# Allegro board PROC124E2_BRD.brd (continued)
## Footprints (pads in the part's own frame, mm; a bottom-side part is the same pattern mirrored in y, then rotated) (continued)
SON6_SN74LVC2G17_40X60_0-6
  rect 0.356x0.203 smd: 1(-0.275,0.5)
  rect 0.305x0.203 smd: 2(-0.3,0) 3(-0.3,-0.5) 4(0.3,-0.5) 5(0.3,0) 6(0.3,0.5)
SON8_25-59_130X130_1
  rect 0.762x0.356 smd: 1(-1.45,0.975) 2(-1.45,0.325) 3(-1.45,-0.325) 4(-1.45,-0.975) 5(1.45,-0.975) 6(1.45,-0.325) 7(1.45,0.325) 8(1.45,0.975)
  rect 1.753x2.515 smd: 9(0,0)
SOT23-5
  rect 0.889x0.559 smd: 1(-1.2,0.95) 2(-1.2,0) 3(-1.2,-0.95) 4(1.2,-0.95) 5(1.2,0.95)
SOT23-6
  rect 1.041x0.61 smd: 1(-1.35,0.95) 2(-1.35,0) 3(-1.35,-0.95) 4(1.35,-0.95) 5(1.35,0) 6(1.35,0.95)
SOT23-6_1-5
  rect 1.092x0.61 smd: 1(-1.35,0.95) 2(-1.35,0) 3(-1.35,-0.95) 4(1.35,-0.95) 5(1.35,0) 6(1.35,0.95)
SOT23-123_1-2
  rect 1.016x0.61 smd: 1(-1.15,0.95) 2(-1.15,-0.95) 3(1.15,0)
SOT553-5_0-6
  rect 0.559x0.229 smd: 1(-0.69,0.5) 2(-0.69,0) 3(-0.69,-0.5) 4(0.69,-0.5) 5(0.69,0.5)
SW4_100X216_200X200_SMD_4-2
  rect 1.27x1.27 smd: 1(-1.27,-2.75) 2(1.27,-2.75) 3(1.27,2.75) 4(-1.27,2.75)
SW16_416131160808_460X230_SMD_2-7
  rect 0.762x1.27 smd: 1(-4.445,-3.81) 2(-3.175,-3.81) 3(-1.905,-3.81) 4(-0.635,-3.81) 5(0.635,-3.81) 6(1.905,-3.81) 7(3.175,-3.81) 8(4.445,-3.81) 9(4.445,3.81) 10(3.175,3.81) 11(1.905,3.81) 12(0.635,3.81) 13(-0.635,3.81) 14(-1.905,3.81) 15(-3.175,3.81) 16(-4.445,3.81)
TFBGA200_MT53E1G16D1FW_400X570_1-1
  round 0.33 smd: A1(-4.4,6.825) A2(-3.6,6.825) A3(-2.8,6.825) A4(-2,6.825) A5(-1.2,6.825) A8(1.2,6.825) A9(2,6.825) A10(2.8,6.825) A11(3.6,6.825) A12(4.4,6.825) AA1(-4.4,-6.175) AA2(-3.6,-6.175) AA3(-2.8,-6.175) AA4(-2,-6.175) AA5(-1.2,-6.175) AA8(1.2,-6.175) AA9(2,-6.175) AA10(2.8,-6.175) AA11(3.6,-6.175) AA12(4.4,-6.175) AB1(-4.4,-6.825) AB2(-3.6,-6.825) AB3(-2.8,-6.825) AB4(-2,-6.825) AB5(-1.2,-6.825) AB8(1.2,-6.825) AB9(2,-6.825) AB10(2.8,-6.825) AB11(3.6,-6.825) AB12(4.4,-6.825) B1(-4.4,6.175) B2(-3.6,6.175) B3(-2.8,6.175) B4(-2,6.175) B5(-1.2,6.175) B8(1.2,6.175) B9(2,6.175) B10(2.8,6.175) B11(3.6,6.175) B12(4.4,6.175) C1(-4.4,5.525) C2(-3.6,5.525) C3(-2.8,5.525) C4(-2,5.525) C5(-1.2,5.525) C8(1.2,5.525) C9(2,5.525) C10(2.8,5.525) C11(3.6,5.525) C12(4.4,5.525) D1(-4.4,4.875) D2(-3.6,4.875) D3(-2.8,4.875) D4(-2,4.875) D5(-1.2,4.875) D8(1.2,4.875) D9(2,4.875) D10(2.8,4.875) D11(3.6,4.875) D12(4.4,4.875) E1(-4.4,4.225) E2(-3.6,4.225) E3(-2.8,4.225) E4(-2,4.225) E5(-1.2,4.225) E8(1.2,4.225) E9(2,4.225) E10(2.8,4.225) E11(3.6,4.225) E12(4.4,4.225) F1(-4.4,3.575) F2(-3.6,3.575) F3(-2.8,3.575) F4(-2,3.575) F5(-1.2,3.575) F8(1.2,3.575) F9(2,3.575) F10(2.8,3.575) F11(3.6,3.575) F12(4.4,3.575) G1(-4.4,2.925) G2(-3.6,2.925) G3(-2.8,2.925) G4(-2,2.925) G5(-1.2,2.925) G8(1.2,2.925) G9(2,2.925) G10(2.8,2.925) G11(3.6,2.925) G12(4.4,2.925) H1(-4.4,2.275) H2(-3.6,2.275) H3(-2.8,2.275) H4(-2,2.275) H5(-1.2,2.275) H8(1.2,2.275) H9(2,2.275) H10(2.8,2.275) H11(3.6,2.275) H12(4.4,2.275) J1(-4.4,1.625) J2(-3.6,1.625) J3(-2.8,1.625) J4(-2,1.625) J5(-1.2,1.625) J8(1.2,1.625) J9(2,1.625) J10(2.8,1.625) J11(3.6,1.625) J12(4.4,1.625) K1(-4.4,0.975) K2(-3.6,0.975) K3(-2.8,0.975) K4(-2,0.975) K5(-1.2,0.975) K8(1.2,0.975) K9(2,0.975) K10(2.8,0.975) K11(3.6,0.975) K12(4.4,0.975) N1(-4.4,-0.975) N2(-3.6,-0.975) N3(-2.8,-0.975) N4(-2,-0.975) N5(-1.2,-0.975) N8(1.2,-0.975) N9(2,-0.975) N10(2.8,-0.975) N11(3.6,-0.975) N12(4.4,-0.975) P1(-4.4,-1.625) P2(-3.6,-1.625) P3(-2.8,-1.625) P4(-2,-1.625) P5(-1.2,-1.625) P8(1.2,-1.625) P9(2,-1.625) P10(2.8,-1.625) P11(3.6,-1.625) P12(4.4,-1.625) R1(-4.4,-2.275) R2(-3.6,-2.275) R3(-2.8,-2.275) R4(-2,-2.275) R5(-1.2,-2.275) R8(1.2,-2.275) R9(2,-2.275) R10(2.8,-2.275) R11(3.6,-2.275) R12(4.4,-2.275) T1(-4.4,-2.925) T2(-3.6,-2.925) T3(-2.8,-2.925) T4(-2,-2.925) T5(-1.2,-2.925) T8(1.2,-2.925) T9(2,-2.925) T10(2.8,-2.925) T11(3.6,-2.925) T12(4.4,-2.925) U1(-4.4,-3.575) U2(-3.6,-3.575) U3(-2.8,-3.575) U4(-2,-3.575) U5(-1.2,-3.575) U8(1.2,-3.575) U9(2,-3.575) U10(2.8,-3.575) U11(3.6,-3.575) U12(4.4,-3.575) V1(-4.4,-4.225) V2(-3.6,-4.225) V3(-2.8,-4.225) V4(-2,-4.225) V5(-1.2,-4.225) V8(1.2,-4.225) V9(2,-4.225) V10(2.8,-4.225) V11(3.6,-4.225) V12(4.4,-4.225) W1(-4.4,-4.875) W2(-3.6,-4.875) W3(-2.8,-4.875) W4(-2,-4.875) W5(-1.2,-4.875) W8(1.2,-4.875) W9(2,-4.875) W10(2.8,-4.875) W11(3.6,-4.875) W12(4.4,-4.875) Y1(-4.4,-5.525) Y2(-3.6,-5.525) Y3(-2.8,-5.525) Y4(-2,-5.525) Y5(-1.2,-5.525) Y8(1.2,-5.525) Y9(2,-5.525) Y10(2.8,-5.525) Y11(3.6,-5.525) Y12(4.4,-5.525)
TO_SOT23-123
  rect 1.016x1.397 smd: 1(-0.95,-1.1) 2(0.95,-1.1) 3(0,1.1)
TP20_SMD
  round 0.457 smd: 1(0,0)
TP_40X65
  round 1.651 hole 1.016: 1(0,0)
TPBGA24_39-37_240X320_1-2
  round 0.356 smd: A2(-1,2) A3(0,2) A4(1,2) A5(2,2) B1(-2,1) B2(-1,1) B3(0,1) B4(1,1) B5(2,1) C1(-2,0) C2(-1,0) C3(0,0) C4(1,0) C5(2,0) D1(-2,-1) D2(-1,-1) D3(0,-1) D4(1,-1) D5(2,-1) E1(-2,-2) E2(-1,-2) E3(0,-2) E4(1,-2) E5(2,-2)
TQFP128_15-74_550X550_1-2
  rect 1.499x0.203 smd: 1(-7.7,6.2) 2(-7.7,5.8) 3(-7.7,5.4) 4(-7.7,5) 5(-7.7,4.6) 6(-7.7,4.2) 7(-7.7,3.8) 8(-7.7,3.4) 9(-7.7,3) 10(-7.7,2.6) 11(-7.7,2.2) 12(-7.7,1.8) 13(-7.7,1.4) 14(-7.7,1) 15(-7.7,0.6) 16(-7.7,0.2) 17(-7.7,-0.2) 18(-7.7,-0.6) 19(-7.7,-1) 20(-7.7,-1.4) 21(-7.7,-1.8) 22(-7.7,-2.2) 23(-7.7,-2.6) 24(-7.7,-3) 25(-7.7,-3.4) 26(-7.7,-3.8) 27(-7.7,-4.2) 28(-7.7,-4.6) 29(-7.7,-5) 30(-7.7,-5.4) 31(-7.7,-5.8) 32(-7.7,-6.2) 65(7.7,-6.2) 66(7.7,-5.8) 67(7.7,-5.4) 68(7.7,-5) 69(7.7,-4.6) 70(7.7,-4.2) 71(7.7,-3.8) 72(7.7,-3.4) 73(7.7,-3) 74(7.7,-2.6) 75(7.7,-2.2) 76(7.7,-1.8) 77(7.7,-1.4) 78(7.7,-1) 79(7.7,-0.6) 80(7.7,-0.2) 81(7.7,0.2) 82(7.7,0.6) 83(7.7,1) 84(7.7,1.4) 85(7.7,1.8) 86(7.7,2.2) 87(7.7,2.6) 88(7.7,3) 89(7.7,3.4) 90(7.7,3.8) 91(7.7,4.2) 92(7.7,4.6) 93(7.7,5) 94(7.7,5.4) 95(7.7,5.8) 96(7.7,6.2)
  rect 0.203x1.499 smd: 33(-6.2,-7.7) 34(-5.8,-7.7) 35(-5.4,-7.7) 36(-5,-7.7) 37(-4.6,-7.7) 38(-4.2,-7.7) 39(-3.8,-7.7) 40(-3.4,-7.7) 41(-3,-7.7) 42(-2.6,-7.7) 43(-2.2,-7.7) 44(-1.8,-7.7) 45(-1.4,-7.7) 46(-1,-7.7) 47(-0.6,-7.7) 48(-0.2,-7.7) 49(0.2,-7.7) 50(0.6,-7.7) 51(1,-7.7) 52(1.4,-7.7) 53(1.8,-7.7) 54(2.2,-7.7) 55(2.6,-7.7) 56(3,-7.7) 57(3.4,-7.7) 58(3.8,-7.7) 59(4.2,-7.7) 60(4.6,-7.7) 61(5,-7.7) 62(5.4,-7.7) 63(5.8,-7.7) 64(6.2,-7.7) 97(6.2,7.7) 98(5.8,7.7) 99(5.4,7.7) 100(5,7.7) 101(4.6,7.7) 102(4.2,7.7) 103(3.8,7.7) 104(3.4,7.7) 105(3,7.7) 106(2.6,7.7) 107(2.2,7.7) 108(1.8,7.7) 109(1.4,7.7) 110(1,7.7) 111(0.6,7.7) 112(0.2,7.7) 113(-0.2,7.7) 114(-0.6,7.7) 115(-1,7.7) 116(-1.4,7.7) 117(-1.8,7.7) 118(-2.2,7.7) 119(-2.6,7.7) 120(-3,7.7) 121(-3.4,7.7) 122(-3.8,7.7) 123(-4.2,7.7) 124(-4.6,7.7) 125(-5,7.7) 126(-5.4,7.7) 127(-5.8,7.7) 128(-6.2,7.7)
TSSOP8_25-59_125X180_1-2
  rect 1.499x0.457 smd: 1(-2.9,0.975) 2(-2.9,0.325) 3(-2.9,-0.325) 4(-2.9,-0.975) 5(2.9,-0.975) 6(2.9,-0.325) 7(2.9,0.325) 8(2.9,0.975)
TSSOP14_25-59_205X180_1-2
  rect 1.499x0.457 smd: 1(-2.9,1.95) 2(-2.9,1.3) 3(-2.9,0.65) 4(-2.9,0) 5(-2.9,-0.65) 6(-2.9,-1.3) 7(-2.9,-1.95) 8(2.9,-1.95) 9(2.9,-1.3) 10(2.9,-0.65) 11(2.9,0) 12(2.9,0.65) 13(2.9,1.3) 14(2.9,1.95)
TSSOP16_25-59_205X180
  rect 1.6x0.356 smd: 1(-2.8,2.275) 2(-2.8,1.625) 3(-2.8,0.975) 4(-2.8,0.325) 5(-2.8,-0.325) 6(-2.8,-0.975) 7(-2.8,-1.625) 8(-2.8,-2.275) 9(2.8,-2.275) 10(2.8,-1.625) 11(2.8,-0.975) 12(2.8,-0.325) 13(2.8,0.325) 14(2.8,0.975) 15(2.8,1.625) 16(2.8,2.275)
TSSOP24_25-59_315X180_1-2
  rect 1.448x0.457 smd: 1(-2.9,3.575) 2(-2.9,2.925) 3(-2.9,2.275) 4(-2.9,1.625) 5(-2.9,0.975) 6(-2.9,0.325) 7(-2.9,-0.325) 8(-2.9,-0.975) 9(-2.9,-1.625) 10(-2.9,-2.275) 11(-2.9,-2.925) 12(-2.9,-3.575) 13(2.9,-3.575) 14(2.9,-2.925) 15(2.9,-2.275) 16(2.9,-1.625) 17(2.9,-0.975) 18(2.9,-0.325) 19(2.9,0.325) 20(2.9,0.975) 21(2.9,1.625) 22(2.9,2.275) 23(2.9,2.925) 24(2.9,3.575)
UFDFPN8_M24512_120X80_0-6
  rect 0.61x0.305 smd: 1(-1.3,0.75) 2(-1.3,0.25) 3(-1.3,-0.25) 4(-1.3,-0.75) 5(1.3,-0.75) 6(1.3,-0.25) 7(1.3,0.25) 8(1.3,0.75)
  rect 1.194x1.397 smd: 9(0,0)
unnamed#2
  round 2.616 hole 2.743 unplated: (0,0)
unnamed#3
  round 1.549 hole 1.676 unplated: (-9.962,9.962) (-9.962,-9.962) (9.962,9.962) (9.962,-9.962)
  round 0.737 hole 0.864 unplated: (-4.882,-9.962) (9.962,7.422)
UQFN10_19-68_80X60_0-6
  rect 0.584x0.305 smd: 1(-0.635,0.75) 4(-0.635,-0.75) 6(0.635,-0.75) 9(0.635,0.75)
  rect 0.584x0.254 smd: 2(-0.635,0.25) 3(-0.635,-0.25) 7(0.635,-0.25) 8(0.635,0.25)
  rect 0.305x0.635 smd: 5(0,-0.86) 10(0,0.86)
UQFN12_TXB0104RUT_70X80_0-6
  custom 0.102x0.102 smd: 1(-0.65,0.8)
  rect 0.61x0.203 smd: 2(-0.65,0.4) 3(-0.65,0) 4(-0.65,-0.4) 5(-0.65,-0.8) 7(0.65,-0.8) 8(0.65,-0.4) 9(0.65,0) 10(0.65,0.4) 11(0.65,0.8)
  rect 0.203x0.61 smd: 6(0,-0.8) 12(0,0.8)
UQFN16_TMUX1574_70X100_0-6
  rect 0.711x0.203 smd: 1(-0.75,0.6)
  rect 0.61x0.203 smd: 2(-0.8,0.2) 3(-0.8,-0.2) 4(-0.8,-0.6) 9(0.8,-0.6) 10(0.8,-0.2) 11(0.8,0.2) 12(0.8,0.6)
  rect 0.203x0.61 smd: 5(-0.6,-1.2) 6(-0.2,-1.2) 7(0.2,-1.2) 8(0.6,-1.2) 13(0.6,1.2) 14(0.2,1.2) 15(-0.2,1.2) 16(-0.6,1.2)
VFBGA153_19-68_460X520_1-1
  round 0.254 smd: A1(-3.25,3.25) A2(-2.75,3.25) A3(-2.25,3.25) A4(-1.75,3.25) A5(-1.25,3.25) A6(-0.75,3.25) A7(-0.25,3.25) A8(0.25,3.25) A9(0.75,3.25) A10(1.25,3.25) A11(1.75,3.25) A12(2.25,3.25) A13(2.75,3.25) A14(3.25,3.25) B2(-2.75,2.75) B3(-2.25,2.75) B4(-1.75,2.75) B5(-1.25,2.75) B6(-0.75,2.75) B7(-0.25,2.75) B8(0.25,2.75) B9(0.75,2.75) B10(1.25,2.75) B11(1.75,2.75) B12(2.25,2.75) B13(2.75,2.75) B14(3.25,2.75) C2(-2.75,2.25) C3(-2.25,2.25) C4(-1.75,2.25) C5(-1.25,2.25) C6(-0.75,2.25) C7(-0.25,2.25) C8(0.25,2.25) C9(0.75,2.25) C10(1.25,2.25) C11(1.75,2.25) C12(2.25,2.25) C13(2.75,2.25) C14(3.25,2.25) D2(-2.75,1.75) D3(-2.25,1.75) D4(-1.75,1.75) D12(2.25,1.75) D13(2.75,1.75) D14(3.25,1.75) E1(-3.25,1.25) E2(-2.75,1.25) E3(-2.25,1.25) E5(-1.25,1.25) E6(-0.75,1.25) E7(-0.25,1.25) E8(0.25,1.25) E9(0.75,1.25) E10(1.25,1.25) E12(2.25,1.25) E13(2.75,1.25) E14(3.25,1.25) F1(-3.25,0.75) F2(-2.75,0.75) F3(-2.25,0.75) F5(-1.25,0.75) F10(1.25,0.75) F12(2.25,0.75) F13(2.75,0.75) F14(3.25,0.75) G1(-3.25,0.25) G2(-2.75,0.25) G3(-2.25,0.25) G5(-1.25,0.25) G10(1.25,0.25) G12(2.25,0.25) G13(2.75,0.25) G14(3.25,0.25) H1(-3.25,-0.25) H2(-2.75,-0.25) H3(-2.25,-0.25) H5(-1.25,-0.25) H10(1.25,-0.25) H12(2.25,-0.25) H13(2.75,-0.25) H14(3.25,-0.25) J1(-3.25,-0.75) J2(-2.75,-0.75) J3(-2.25,-0.75) J5(-1.25,-0.75) J10(1.25,-0.75) J12(2.25,-0.75) J13(2.75,-0.75) J14(3.25,-0.75) K1(-3.25,-1.25) K2(-2.75,-1.25) K3(-2.25,-1.25) K5(-1.25,-1.25) K6(-0.75,-1.25) K7(-0.25,-1.25) K8(0.25,-1.25) K9(0.75,-1.25) K10(1.25,-1.25) K12(2.25,-1.25) K13(2.75,-1.25) K14(3.25,-1.25) L1(-3.25,-1.75) L2(-2.75,-1.75) L3(-2.25,-1.75) L12(2.25,-1.75) L13(2.75,-1.75) L14(3.25,-1.75) M2(-2.75,-2.25) M3(-2.25,-2.25) M4(-1.75,-2.25) M5(-1.25,-2.25) M6(-0.75,-2.25) M7(-0.25,-2.25) M8(0.25,-2.25) M9(0.75,-2.25) M10(1.25,-2.25) M11(1.75,-2.25) M12(2.25,-2.25) M13(2.75,-2.25) M14(3.25,-2.25) N2(-2.75,-2.75) N3(-2.25,-2.75) N4(-1.75,-2.75) N5(-1.25,-2.75) N6(-0.75,-2.75) N7(-0.25,-2.75) N8(0.25,-2.75) N9(0.75,-2.75) N10(1.25,-2.75) N11(1.75,-2.75) N12(2.25,-2.75) N13(2.75,-2.75) N14(3.25,-2.75) P2(-2.75,-3.25) P3(-2.25,-3.25) P4(-1.75,-3.25) P5(-1.25,-3.25) P6(-0.75,-3.25) P7(-0.25,-3.25) P8(0.25,-3.25) P9(0.75,-3.25) P10(1.25,-3.25) P11(1.75,-3.25) P12(2.25,-3.25) P13(2.75,-3.25) P14(3.25,-3.25)
  round 0.203 smd: B1(-3.25,2.75) C1(-3.25,2.25) D1(-3.25,1.75) M1(-3.25,-2.25) N1(-3.25,-2.75) P1(-3.25,-3.25)
VQFN48_19-68_285X285
  rect 0.864x0.305 smd: 1(-3.5,2.75) 2(-3.5,2.25) 3(-3.5,1.75) 4(-3.5,1.25) 5(-3.5,0.75) 6(-3.5,0.25) 7(-3.5,-0.25) 8(-3.5,-0.75) 9(-3.5,-1.25) 10(-3.5,-1.75) 11(-3.5,-2.25) 12(-3.5,-2.75) 25(3.5,-2.75) 26(3.5,-2.25) 27(3.5,-1.75) 28(3.5,-1.25) 29(3.5,-0.75) 30(3.5,-0.25) 31(3.5,0.25) 32(3.5,0.75) 33(3.5,1.25) 34(3.5,1.75) 35(3.5,2.25) 36(3.5,2.75)
  rect 0.305x0.864 smd: 13(-2.75,-3.5) 14(-2.25,-3.5) 15(-1.75,-3.5) 16(-1.25,-3.5) 17(-0.75,-3.5) 18(-0.25,-3.5) 19(0.25,-3.5) 20(0.75,-3.5) 21(1.25,-3.5) 22(1.75,-3.5) 23(2.25,-3.5) 24(2.75,-3.5) 37(2.75,3.5) 38(2.25,3.5) 39(1.75,3.5) 40(1.25,3.5) 41(0.75,3.5) 42(0.25,3.5) 43(-0.25,3.5) 44(-0.75,3.5) 45(-1.25,3.5) 46(-1.75,3.5) 47(-2.25,3.5) 48(-2.75,3.5)
  rect 4.166x4.166 smd: 49(0,0)
VQFN56_TPS65987D_280X280_1
  rect 0.813x0.711 smd: 1(-3.35,2.4) 3(-3.35,1.6) 11(-3.35,-1.6) 13(-3.35,-2.4)
  rect 0.711x0.203 smd: 5(-3.35,1) 6(-3.35,0.6) 7(-3.35,0.2) 8(-3.35,-0.2) 9(-3.35,-0.6) 10(-3.35,-1) 29(3.35,-2.6) 30(3.35,-2.2) 31(3.35,-1.8) 32(3.35,-1.4) 33(3.35,-1) 34(3.35,-0.6) 35(3.35,-0.2) 36(3.35,0.2) 37(3.35,0.6) 38(3.35,1) 39(3.35,1.4) 40(3.35,1.8) 41(3.35,2.2) 42(3.35,2.6)
  rect 0.203x0.711 smd: 15(-2.6,-3.35) 16(-2.2,-3.35) 17(-1.8,-3.35) 18(-1.4,-3.35) 19(-1,-3.35) 20(-0.6,-3.35) 21(-0.2,-3.35) 22(0.2,-3.35) 23(0.6,-3.35) 24(1,-3.35) 25(1.4,-3.35) 26(1.8,-3.35) 27(2.2,-3.35) 28(2.6,-3.35) 43(2.6,3.35) 44(2.2,3.35) 45(1.8,3.35) 46(1.4,3.35) 47(1,3.35) 48(0.6,3.35) 49(0.2,3.35) 50(-0.2,3.35) 51(-0.6,3.35) 52(-1,3.35) 53(-1.4,3.35) 54(-1.8,3.35) 55(-2.2,3.35) 56(-2.6,3.35)
  rect 1.753x2.591 smd: 57(-1.875,1.45)
  rect 1.753x2.54 smd: 58(-1.875,-1.475)
  rect 3.404x5.512 smd: 59(1.05,0)
VQFNHR14_LM61460_160X140_1
  custom 0.175x0.175 smd: 1(-1.675,1.15) 5(-1.675,-1.15)
  rect 0.711x0.254 smd: 2(-1.85,0.525) 4(-1.85,-0.525)
  rect 0.711x0.305 smd: 3(-1.85,0)
  rect 0.254x0.711 smd: 6(-1.125,-1.6) 7(-0.625,-1.6) 13(-0.625,1.6) 14(-1.125,1.6)
  rect 0.406x0.991 smd: 8(0.45,-1.45) 12(0.45,1.45)
  custom 0.2x0.2 smd: 9(1.6,-1.15) 11(1.6,1.15)
  rect 2.388x0.406 smd: 10(1,0)
VQFNHR15_TPS630701_100X120_1
  rect 0.61x0.254 smd: 1(-1.15,0.75) 2(-1.15,0.25) 3(-1.15,-0.25) 4(-1.15,-0.75)
  rect 0.254x0.61 smd: 5(-0.725,-1.4) 6(-0.225,-1.4) 14(-0.225,1.4) 15(-0.725,1.4)
  rect 0.838x0.711 smd: 7(0.525,-1.4) 12(0.525,1.4)
  rect 1.448x0.356 smd: 9(0.775,-0.5) 11(0.775,0.5)
  rect 1.803x0.356 smd: 10(0.6,0)
VSONHR6_TPS62826_60X60_1
  rect 0.711x0.356 smd: 1(-0.65,0.5) 2(-0.65,0) 3(-0.65,-0.5)
  rect 0.991x0.203 smd: 4(0.45,-0.5) 5(0.45,0) 6(0.45,0.5)
VSSOP8_19-68_85X95
  rect 1.041x0.305 smd: 1(-1.65,0.75) 2(-1.65,0.25) 3(-1.65,-0.25) 4(-1.65,-0.75) 5(1.65,-0.75) 6(1.65,-0.25) 7(1.65,0.25) 8(1.65,0.75)
VSSOP8_19-68_85X95_0-9
  rect 0.838x0.305 smd: 1(-1.55,0.75) 2(-1.55,0.25) 3(-1.55,-0.25) 4(-1.55,-0.75) 5(1.55,-0.75) 6(1.55,-0.25) 7(1.55,0.25) 8(1.55,0.75)
WSON6_19-68_60X60
  rect 0.965x0.305 smd: 1(-0.65,0.5) 2(-0.65,0) 3(-0.65,-0.5) 4(0.65,-0.5) 5(0.65,0) 6(0.65,0.5)
WSON6_CSD13202Q2_80X80_0-8
  rect 0.457x0.305 smd: 1(-0.975,0.65) 2(-0.975,0) 3(-0.975,-0.65) 4(0.975,-0.65) 5(0.975,0) 6(0.975,0.65)
  rect 0.762x0.305 smd: 7(0.095,-0.65)
  rect 0.991x0.94 smd: 8(0,0.325)
WSON8_19-68_80X80_0-8
  rect 0.711x0.305 smd: 1(-1.05,0.75) 2(-1.05,0.25) 3(-1.05,-0.25) 4(-1.05,-0.75) 5(1.05,-0.75) 6(1.05,-0.25) 7(1.05,0.25) 8(1.05,0.75)
  rect 0.965x1.702 smd: 9(0,0)
WSON10_19-68_80X120_0-8
  rect 0.711x0.305 smd: 1(-1.05,1) 2(-1.05,0.5) 3(-1.05,0) 4(-1.05,-0.5) 5(-1.05,-1) 6(1.05,-1) 7(1.05,-0.5) 8(1.05,0) 9(1.05,0.5) 10(1.05,1)
  rect 0.94x2.489 smd: 11(0,0)
X2SON3_ESD122DMX_30X40_0-4
  rect 0.203x0.203 smd: 1(-0.15,0) 2(0.15,-0.34) 3(0.15,0.34)
X2SON4_TLV71318P_40X40_0-4
  custom 0.077x0.077 smd: 1(-0.43,0.325) 2(-0.43,-0.325) 3(0.43,-0.325) 4(0.43,0.325)
  rect 0.584x0.584 smd rot 45: 5(0,0)
X2SON5_TLV7021_30X30_0-4
  custom 0.08x0.08 smd: 1(-0.39,0.24) 2(-0.39,-0.24) 4(0.39,-0.24) 5(0.39,0.24)
  rect 0.356x0.356 smd rot 135: 3(0,0)
X2SON8_15-74_70X50
  rect 0.838x0.203 smd: 1(-0.55,0.6) 2(-0.55,0.2) 3(-0.55,-0.2) 4(-0.55,-0.6) 5(0.55,-0.6) 6(0.55,-0.2) 7(0.55,0.2) 8(0.55,0.6)
X2SON8_TXS0102_40X60_0-4
  rect 0.61x0.178 smd: 1(-0.4,0.525)
  rect 0.508x0.178 smd: 2(-0.45,0.175) 3(-0.45,-0.175) 4(-0.45,-0.525) 5(0.45,-0.525) 6(0.45,-0.175) 7(0.45,0.175) 8(0.45,0.525)
XTAL4_XRCGB-FM_80X60_SMD_0-7
  rect 0.762x0.711 smd: 1(-0.675,-0.5) 2(0.675,-0.5) 3(0.675,0.5) 4(-0.675,0.5)
XTAL_ABM3_205X130_SMD_1-4
  rect 1.803x2.413 smd: 1(-1.9,0) 2(1.9,0)
XTAL_ECS-32_130X60_SMD_0-9
  rect 1.118x1.905 smd: 1(-1.25,0) 2(1.25,0)

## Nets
3V3_SYS_EN: R442.2 U67.7(EN/SYNC)
AGND_AUD: C124.2 C126.2 C132.2 C133.2 C398.2 C399.2 C402.2 C403.2 FL11.1 J14.4 TP67.1(TP) U66.15(AVSS_ADC) U66.20(DRVSS.1) U66.21(DRVSS.2) U66.26(AVSS_DAC) U66.49(TPAD)
DGND: C1.2 C2.2 C3.1 C4.2 C5.2 C6.1 C7.1 C8.1 C9.1 C10.1 C11.1 C12.2 C13.2 C14.2 C15.1 C16.2 C17.1 C18.2 C19.2 C25.2 C26.2 C27.2 C28.2 C31.2 C32.2 C33.2 C34.1 C35.2 C36.2 C37.2 C38.2 C39.2 C40.2 C41.1 C42.2 C43.1 C44.2 C45.2 C46.2 C47.2 C48.1 C49.1 C50.2 C51.2 C52.2 C53.2 C54.1 C55.2 C56.2 C57.2 C59.2 C60.2 C61.2 C62.2 C63.2 C64.2 C66.2 C67.2 C68.1 C69.1 C70.2 C71.2 C72.1 C73.2 C74.2 C75.2 C76.2 C77.1 C78.2 C79.1 C80.1 C81.1 C82.2 C83.1 C84.1 C85.2 C86.2 C87.2 C88.2 C89.1 C90.1 C91.1 C92.1 C93.1 C94.1 C95.1 C96.2 C97.1 C98.2 C99.1 C100.2 C101.2 C102.2 C103.1 C104.1 C105.1 C106.2 C107.2 C108.1 C109.2 C110.2 C111.2 C112.2 C113.1 C114.1 C115.2 C116.1 C117.2 C118.1 C119.2 C120.2 C121.2 C122.2 C123.2 C125.2 C127.2 C128.2 C129.1 C130.2 C131.1 C134.2 C135.2 C136.2 C137.2 C138.2 C139.2 C140.1 C141.2 C142.2 C145.2 C146.2 C147.2 C148.2 C149.2 C150.2 C151.1 C152.1 C153.1 C154.1 C155.1 C156.2 C157.2 C158.2 C159.2 C160.1 C161.2 C162.2 C163.2 C164.2 C165.1 C166.1 C167.1 C168.1 C169.2 C170.1 C171.1 C172.2 C173.1 C174.2 C175.2 C176.1 C177.2 C178.1 C179.1 C180.1 C181.1 C182.1 C183.1 C184.1 C185.2 C186.2 C187.2 C188.1 C189.2 C190.1 C191.2 C192.2 C193.1 C194.2 C195.1 C196.2 C197.2 C198.2 C201.2 C202.2 C203.2 C204.1 C205.2 C206.2 C208.1 C209.2 C212.2 C213.2 C214.2 C215.2 C217.2 C219.2 C220.2 C221.2 C222.2 C223.2 C225.2 C226.2 C227.2 C230.2 C232.1 C234.2 C235.2 C236.2 C237.2 C238.2 C239.2 C240.2 C241.2 C242.2 C244.2 C246.2 C247.2 C248.2 C249.2 C252.2 C253.2 C254.2 C255.2 C256.2 C257.2 C258.2 C259.2 C260.1 C261.2 C262.2 C263.2 C264.2 C265.2 C266.2 C267.2 C268.2 C269.2 C270.2 C271.2 C272.2 C273.2 C274.2 C275.2 C277.2 C278.2 C279.2 C281.2 C282.2 C284.2 C285.2 C286.2 C287.2 C288.2 C289.2 C290.2 C291.2 C292.2 C293.2 C294.2 C295.2 C296.2 C297.2 C298.2 C299.2 C300.2 C301.2 C302.2 C303.2 C304.2 C305.1 C306.2 C307.2 C308.2 C309.2 C310.2 C311.2 C312.2 C313.2 C314.2 C315.2 C316.2 C317.2 C318.2 C319.2 C320.1 C321.2 C322.2 C323.2 C324.2 C325.2 C326.2 C327.2 C328.2 C329.2 C330.1 C331.1 C332.1 C333.2 C334.1 C335.2 C336.1 C337.1 C338.2 C339.1 C342.2 C343.2 C344.2 C345.2 C346.1 C347.1 C348.2 C349.2 C350.1 C351.2 C352.2 C353.1 C354.1 C355.1 C356.1 C357.1 C359.2 C360.2 C361.1 C362.2 C363.1 C364.2 C365.2 C366.2 C367.1 C368.1 C369.1 C370.2 C372.2 C373.2 C375.2 C376.2 C377.1 C378.2 C379.1 C380.2 C381.1 C382.2 C383.2 C384.2 C385.2 C386.2 C387.2 C388.2 C389.2 C390.2 C391.2 C393.2 C395.2 C397.2 C400.2 C401.2 C406.2 C407.2 C410.2 C411.2 C412.2 C413.1 C414.2 C415.2 C416.2 C417.1 C418.1 C419.2 C420.2 C421.2 C422.2 C423.2 C424.2 C426.1 C427.2 C428.1 C430.1 C431.2 C432.1 C433.1 C434.1 C435.1 C436.1 C437.1 C438.1 C439.2 C440.2 C441.1 C442.1 C443.1 C444.2 C445.1 C446.1 C447.1 C448.1 C449.1 C450.2 C451.1 C452.1 C453.1 C454.1 C455.1 C456.1 C457.1 C458.1 C459.2 C460.1 C461.1 C462.2 C463.1 C464.1 C465.1 C466.1 C467.2 C468.1 C469.1 C470.2 C471.1 C472.1 C473.1 C474.1 C475.2 C476.1 C477.1 C478.1 C479.1 C480.1 C507.2 C531.2 C533.2 C534.2 C535.2 C562.1 C563.2 C564.2 C565.2 C566.2 C567.2 C568.2 C569.2 C570.2 C571.2 C572.2 C573.2 C574.2 C575.2 C576.2 C577.2 C578.2 C579.2 C580.2 C581.2 C582.2 C583.2 C584.2 C585.2 C586.2 C587.2 C588.2 D1.1 D2.1(A) D3.1(A) D4.1 D5.2(ANODE) D6.2(ANODE) D7.1(GND) D8.1 D9.1 D10.2(ANODE) D11.2(ANODE) D12.1 D13.1 FL6.1 FL11.2 FL17.2 J1.12 J1.16 J1.24 J1.SH1 J1.SH2 J1.SH3 J1.SH4 J2.1(GND#1) J2.7(GND#7) J2.18(GND#18) J2.33(GND#33) J2.39(GND#39) J2.45(GND#45) J2.51(GND#51) J2.57(GND#57) J2.63(GND#63) J2.69(GND#69) J2.75(GND#75) J2.SH1 J2.SH2 J3.6 J3.9 J3.14 J3.20 J3.25 J3.34 J5.2 J5.5 J5.8 J5.11 J5.17 J7.1(CH-GND) J9.4(GND) J10.2 J10.3 J10.7 J10.9 J10.14 J10.15 J10.20 J10.27 J11.2 J13.A1(GND#A1) J13.A12(GND#A12) J13.B1(GND#B1) J13.B12(GND#B12) J15.A1(GND#A1) J15.A12(GND#A12) J15.B1(GND#B1) J15.B12(GND#B12) J17.5(GND) J18.5(GND) J19.10 J19.12 J19.16 J19.20 J21.6(VSS) J21.SH1 J21.SH2 J21.SH3 J21.SH4 J22.6 J22.7 J22.10 J22.13 J22.16 J22.19 J22.22 J22.25 J22.28 J22.31 J22.34 J22.37 J22.40 J23.2 J23.10 J24.7 J24.16 J24.25 J24.34 J24.40 J24.41 J24.42 J27.1(CH-GND) LD6.1(CATHODE) LD8.1(CATHODE) LD9.1(CATHODE) LD11.1(CATHODE) LD12.1(CATHODE) Q1.4(S1) Q1.7(S2) Q3.4(S1) Q3.7(S2) Q4.3(D) Q5.4(S1) Q5.7(S2) Q6.4(S1) Q6.7(S2) Q7.4(S1) Q7.7(S2) Q8.2(EMITTER) Q9.4(S1) Q9.7(S2) Q12.3(D) Q13.3(D) Q14.4(S1) Q14.7(S2) Q15.4(S1) Q15.7(S2) Q19.4(S1) Q19.7(S2) Q20.4(S1) Q20.7(S2) Q21.4(S1) Q21.7(S2) R4.2 R5.1 R7.2 R11.1 R13.2 R20.2 R28.1 R32.1 R47.2 R51.2 R59.1 R66.1 R77.1 R81.1 R83.1 R94.1 R104.2 R115.2 R120.2 R124.2 R131.2 R137.2 R140.2 R142.1 R143.2 R152.2 R153.2 R156.2 R157.2 R159.2 R162.1 R170.1 R176.2 R180.1 R183.2 R184.2 R185.2 R186.2 R187.2 R188.2 R189.2 R190.2 R191.2 R192.2 R193.2 R194.2 R195.2 R196.2 R197.2 R198.2 R199.2 R201.2 R206.2 R237.1 R240.1 R241.1 R242.1 R244.1 R245.1 R246.1 R247.2 R254.2 R260.1 R264.1 R272.2 R280.1 R281.1 R290.1 R292.1 R293.1 R296.1 R300.1 R302.2 R303.2 R305.2 R309.2 R338.2 R339.2 R345.2 R354.2 R356.1 R361.2 R362.1 R363.1 R364.1 R366.2 R368.1 R375.2 R378.2 R379.2 R390.2 R400.2 R411.1 R417.2 R423.2 R435.1 R437.1 R441.2 R448.2 R450.2 R454.2 R455.2 R456.1 R460.2 R466.2 R469.1 R470.1 R478.2 R481.2 R486.2 R488.2 R490.1 R491.1 R504.2 R509.1 R513.1 R514.1 R517.1 R519.2 R533.1 R548.1 R556.1 R563.1 R564.1 R569.1 R570.1 R571.1 R572.1 R574.1 R576.1 R631.1 R633.1 R635.1 R636.2 R637.1 R638.1 R639.2 R643.1 R649.1 R659.2 R661.2 SW1.1 SW1.4 SW2.1 SW2.4 SW5.1 SW5.4 SW6.1 SW6.4 TP1.1(TP) TP11.1(TP) TP22.1(TP) TP32.1(TP) TP75.1(TP) TP92.1(TP) U1.2(GND) U2.4(GND) U3.25(GND) U3.33(EP) U4.7(GND) U5.2(GND) U6.4(GND) U7.4(GND) U8.3(GND) U9.2(GND) U10.B3(GND) U10.C1(VSSQ#C1) U10.E5(VSSQ#E5) U11.43(CGND) U11.55(RSVDL) U11.57(IOGND) U11.63(AGND) U11.70(VDDQ) U11.73(PAD) U12.A1(VSS#A1) U12.A4(VSS#A4) U12.A21(VSS#A21) U12.AA1(VSS#AA1) U12.AA9(VSS#AA9) U12.AA12(VSS#AA12) U12.AA15(VSS#AA15) U12.AA21(VSS#AA21) U12.D4(VSS#D4) U12.D11(VSS#D11) U12.D19(VSS#D19) U12.E2(VSS#E2) U12.F4(VSS#F4) U12.F9(VSS#F9) U12.F11(VSS#F11) U12.F13(VSS#F13) U12.F15(VSS#F15) U12.G6(VSS#G6) U12.G9(VSS#G9) U12.G16(VSS#G16) U12.H1(VSS#H1) U12.H6(VSS#H6) U12.H13(VSS#H13) U12.J6(VSS#J6) U12.J10(VSS#J10) U12.J12(VSS#J12) U12.J14(VSS#J14) U12.J16(VSS#J16) U12.K3(VSS#K3) U12.K6(VSS#K6) U12.K8(VSS#K8) U12.K13(VSS#K13) U12.L1(VSS#L1) U12.L6(VSS#L6) U12.L10(VSS#L10) U12.L12(VSS#L12) U12.L14(VSS#L14) U12.L16(VSS#L16) U12.M6(VSS#M6) U12.M9(VSS#M9) U12.M11(VSS#M11) U12.M16(VSS#M16) U12.M18(VSS#M18) U12.N6(VSS#N6) U12.N12(VSS#N12) U12.N14(VSS#N14) U12.P1(VSS#P1) U12.P3(VSS#P3) U12.P6(VSS#P6) U12.P10(VSS#P10) U12.P13(VSS#P13) U12.P15(VSS#P15) U12.P16(VSS#P16) U12.R5(VSS#R5) U12.R7(VSS#R7) U12.R8(VSS#R8) U12.R16(VSS#R16) U12.T3(VSS#T3) U12.T6(VSS#T6) U12.T7(VSS#T7) U12.T9(VSS#T9) U12.T10(VSS#T10) U12.T12(VSS#T12) U12.T15(VSS#T15) U12.U5(VSS#U5) U12.U8(VSS#U8) U12.U10(VSS#U10) U12.U13(VSS#U13) U12.V11(VSS#V11) U12.V14(VSS#V14) U12.V19(VSS#V19) U12.W7(VSS#W7) U12.W10(VSS#W10) U12.W13(VSS#W13) U12.Y3(VSS#Y3) U12.Y4(VSS#Y4) U12.Y6(VSS#Y6) U12.Y11(VSS#Y11) U12.Y14(VSS#Y14) U13.2(GND) U14.4(GND) U15.5(GND) U16.B3(A0) U16.C1(GND) U17.B3(A0) U17.C1(GND) U17.C3(A1) U18.2(GND) U18.5(EP) U19.4(GND) U20.A3(VSS#A3) U20.A10(VSS#A10) U20.AB3(VSS#AB3) U20.AB5(VSS#AB5) U20.AB8(VSS#AB8) U20.AB10(VSS#AB10) U20.C1(VSS#C1) U20.C5(VSS#C5) U20.C8(VSS#C8) U20.C12(VSS#C12) U20.D2(VSS#D2) U20.D4(VSS#D4) U20.D9(VSS#D9) U20.D11(VSS#D11) U20.E1(VSS#E1) U20.E5(VSS#E5) U20.E8(VSS#E8) U20.E12(VSS#E12) U20.G1(VSS#G1) U20.G3(VSS#G3) U20.G5(VSS#G5) U20.G8(VSS#G8) U20.G10(VSS#G10) U20.G12(VSS#G12) U20.J1(VSS#J1) U20.J3(VSS#J3) U20.J10(VSS#J10) U20.J12(VSS#J12) U20.K2(VSS#K2) U20.K4(VSS#K4) U20.K9(VSS#K9) U20.K11(VSS#K11) U20.N2(VSS#N2) U20.N4(VSS#N4) U20.N9(VSS#N9) U20.N11(VSS#N11) U20.P1(VSS#P1) U20.P3(VSS#P3) U20.P10(VSS#P10) U20.P12(VSS#P12) U20.T1(VSS#T1) U20.T3(VSS#T3) U20.T5(VSS#T5) U20.T8(VSS#T8) U20.T10(VSS#T10) U20.T12(VSS#T12) U20.V1(VSS#V1) U20.V5(VSS#V5) U20.V8(VSS#V8) U20.V12(VSS#V12) U20.W2(VSS#W2) U20.W4(VSS#W4) U20.W9(VSS#W9) U20.W11(VSS#W11) U20.Y1(VSS#Y1) U20.Y5(VSS#Y5) U20.Y8(VSS#Y8) U20.Y12(VSS#Y12) U21.A6(VSS#A6) U21.C4(VSSQ#C4) U21.E7(VSS#E7) U21.G5(VSS#G5) U21.H10(VSS#H10) U21.J5(VSS#J5) U21.K8(VSS#K8) U21.N2(VSSQ#N2) U21.N5(VSSQ#N5) U21.P4(VSSQ#P4) U21.P6(VSSQ#P6) U22.15(AGND) U22.33(PGND) U23.2(GND) U24.2(GND) U25.3(GND) U26.8(GND) U27.4(GND) U28.4(VSS) U28.9(EP) U29.5(GND) U29.9(EP) U30.4(GND) U31.2(GND) U32.4(GND) U33.4(GND) U33.10(PGND) U33.15(VSEL) U34.3(GND) U35.4(GND) U36.10(GNDA) U36.17(GND#17) U36.48(GND#48) U36.55(GND#55) U36.58(GND#58) U36.64(W\A\K\E\) U36.66(XOSC0) U36.80(GND#80) U36.114(GND#114) U37.1(GND1) U37.5(GND2) U37.10(AGND) U37.11(GND3) U37.13(TEST) U37.15(GND4) U37.25(GND5) U37.35(GND6) U37.47(GND7) U37.51(GND8) U38.1(ANODE) U39.8(GND) U40.6(GND) U41.3(GND) U42.8(GND) U43.8(GND) U44.10(GND1) U44.11(GND2) U45.B1(GND) U46.B1(GND) U47.3(GND) U48.2(GND) U50.6(GND1) U50.14(GND2) U50.19(GND3) U52.2(GND) U55.49(GND) U56.2(GND) U56.5(EP) U57.4(GND) U58.C1(GND) U59.2(GND) U60.C1(GND) U61.C1(GND) U62.3(GND) U63.C1(GND) U63.C3(A1) U64.2(GND) U65.B1(GND) U66.42(DVSS) U66.43(SELECT) U67.3(AGND) U67.9(PGND1) U67.11(PGND2) U68.20(GND#20) U68.51(GND#51) U68.59(GND#59) U69.1(GND#1) U69.2(GND#2) U69.3(GND#3) U69.7(GND#7) U70.25(GND) U70.33(EP) U71.3(GND) U72.2(GND) U73.11(GND1) U73.12(GND2) U73.13(GND3) U73.25(EP) U74.25(GND) U74.33(EP) U75.11(GND1) U75.12(GND2) U75.13(GND3) U75.25(EP) U76.3(GND) U77.1(GND#1) U77.2(GND#2) U77.3(GND#3) U77.7(GND#7) U78.6(GND) U78.9(PAD) U79.4(GND) U80.3(GND) U81.4(GND) U82.3(A2) U82.5(GND) U82.6(B2) U83.1(1\O\E\) U83.10(GND1) U83.11(GND2) U83.16(2\O\E\) U84.10(GND1) U84.11(GND2) U85.4(GND) U86.5(VSS) U87.10(GND1) U87.11(GND2) U88.3(GND) U89.2(GND) U90.3(GND) U91.1(1\O\E\) U91.10(GND1) U91.11(GND2) U91.16(2\O\E\) U92.1(1\O\E\) U92.7(1A2) U92.9(2A2) U92.10(GND1) U92.11(GND2) U92.12(2B2) U92.14(1B2) U92.16(2\O\E\) U93.1(PGND) U93.5(FB) U93.6(AGND) U93.11(EP) U94.3(GND) U94.7(EP) U95.3(A2) U95.5(GND) U95.6(B2) U96.1(1\O\E\) U96.10(GND1) U96.11(GND2) U96.16(2\O\E\) U97.2(GND) U98.11(GND) U98.21(PAD) U125.A1(GND) U127.49(GND) U128.2(GND) Y1.2 Y1.4 Y3.2 Y3.4
VBUS_5V0_TYPEA1: C110.1 C375.1 J9.1(VCC) R119.2 U23.4(OUT)
VBUS_TYPEC1: C127.1 C393.1 C397.1 J13.A4(VBUS1) J13.A9(VBUS2) J13.B4(VBUS3) J13.B9(VBUS4) R165.1 U68.13(VBUS1) U69.4(IN1) U69.5(IN2) U69.6(IN3)
VBUS_TYPEC2: C134.1 C401.1 C407.1 C423.1 C424.1 C425.1 C532.1 J15.A4(VBUS1) J15.A9(VBUS2) J15.B4(VBUS3) J15.B9(VBUS4) Q11.4(D1) Q11.7(D2) R147.2 R214.1 R484.1 R593.2 U68.3(VBUS2) U77.4(IN1) U77.5(IN2) U77.6(IN3)
VCC1V1: C103.2 C107.1 L3.2 R129.2 R578.2 TP49.1(TP) U22.24(FB_B3)
VCC1V8_CLKBUF: C8.2 C9.2 C10.2 C11.2 FL1.2 R17.2 R27.2 U5.4(VDD) U6.6(VDD)
VCC1V8_SYS: C3.2 C17.2 C18.1 C19.1 C73.1 C82.1 C89.2 C112.1 C179.2 C184.2 C203.1 C209.1 C345.1 C364.1 C365.1 C417.2 FL1.1 L2.2 R35.2 R37.2 R107.1 R108.1 R109.1 R110.1 R111.1 R112.1 R113.1 R114.1 R116.1 R121.2 R138.1 R262.2 R282.2 R283.2 R284.2 R285.2 R286.2 R287.2 R304.2 R319.2 R320.2 R321.2 R322.2 R323.2 R324.2 R325.2 R326.2 R332.2 R333.2 R398.1 R401.1 R434.2 R471.1 R582.1 TP44.1(TP) U2.1(VCCA) U8.5(VCC) U10.B4(VCC) U10.D1(VCCQ#D1) U10.E4(VCCQ#E4) U19.1(VCCA) U21.C6(VCCQ#C6) U21.M4(VCCQ#M4) U21.N4(VCCQ#N4) U21.P3(VCCQ#P3) U21.P5(VCCQ#P5) U22.20(PVIN_LDO2) U22.32(FB_B2) U25.5(VCC) U40.1(VCCA) U44.2(VCCB) U72.5(VCC)
VCC2V5_PG: R383.1 R386.1 U57.2(PG)
VCC3V3_EXP: C192.1 C195.2 C196.1 J3.1 J3.17 R294.1 R295.1 R297.1 R298.1 R299.1 U46.A1(VOUT)
VCC3V3_PRU: C380.1 C381.2 C384.1 J11.1 R432.1 U65.A1(VOUT)
VCC3V3_TA: C470.1 L10.2 R539.2 R559.2 TP91.1(TP) U93.8(SLEEP) U93.10(VOS)
VCC3V3_XDS: C155.2 C158.1 C164.1 C172.1 C174.1 C175.1 C429.1 C431.1 C439.1 C449.2 C451.2 C452.2 C453.2 R215.2 R248.1 R249.1 R250.1 R255.1 R487.1 R497.2 R507.2 R511.2 R515.2 R518.2 TP81.1(TP) U36.7(VDD#7) U36.8(VDDA) U36.16(VDD#16) U36.26(VDD#26) U36.28(VDD#28) U36.39(VDD#39) U36.47(VDD#47) U36.51(VDD#51) U36.52(VDD#52) U36.69(VDD#69) U36.79(VDD#79) U36.90(VDD#90) U36.101(VDD#101) U36.113(VDD#113) U36.122(VDD#122) U78.3(OUT1) U78.4(OUT2) U82.8(VCCB) U84.2(VCCB) U85.8(VCCB)
VCC3V3_XDS_TA: C149.1 C150.1 C418.2 C428.2 C430.2 C459.1 C462.1 J24.1 J24.2 J24.3 R200.2 R221.2 R222.2 R223.2 R224.2 R225.2 R226.2 R227.2 R228.2 R229.2 R230.2 R231.2 R232.2 R233.2 R234.2 R235.2 R236.2 R248.2 R479.1 R480.1 R483.2 R485.2 R489.2 R520.2 R523.2 R524.2 R537.1 R539.1 R541.2 R542.2 R543.2 R555.1 U32.1(VCCA) U34.5(VCC) U73.1(VCCA) U74.27(VCCP) U74.31(VCC) U75.1(VCCA)
VCC5V0_EXP: C185.1 C190.2 C191.1 J3.2 J3.4 U45.A1(VOUT)
VCC_0V85: C100.1 C369.2 R136.2 TP51.1(TP) U22.19(VLDO2)
VCC_1V8_AUD: C388.1 C389.1 R434.1 U66.36(DVDD.1)
VCC_1V8_FT4232: C165.2 C166.2 C446.2 C450.1 U37.12(VCORE#12) U37.37(VCORE#37) U37.49(VREGOUT) U37.64(VCORE#64)
VCC_3V3_AUD: C132.1 C133.1 C382.1 C383.1 C385.1 C398.1 C399.1 C402.1 C403.1 C412.1 R422.1 R425.1 R426.1 R451.2 R457.1 U64.4(VCC) U66.16(DRVDD.1) U66.17(DRVDD.2) U66.24(DRVDD.3) U66.25(AVDD_DAC) U66.44(IOVDD) U71.5(VCC)
VCC_3V3_FB: C396.2 R445.2 R450.1 U67.4(FB)
VCC_3V3_FT4232: C160.2 C170.2 C171.2 C438.2 C445.2 C461.2 C463.2 C467.1 C469.2 C472.2 FL19.2 FL20.2 LD10.2(ANODE) R499.2 R500.2 R501.2 U37.20(VCCIO#20) U37.31(VCCIO#31) U37.42(VCCIO#42) U37.50(VREGIN) U37.56(VCCIO#56) U83.2(VCCB) U86.8(VCC) U91.2(VCCB) U92.2(VCCB) U94.1(OUT) U96.2(VCCB)
VCC_3V3_MAIN: C76.1 C84.2 C85.1 C117.1 C118.2 C123.1 C350.2 C354.2 C359.1 C361.2 C363.2 C390.1 C411.1 C415.1 C531.1 FL14.1 L9.2 R105.1 R210.2 R382.1 R387.1 R404.2 R440.1 R444.1 R445.1 R586.1 TP56.1(TP) U22.4(PVIN_B1_1) U22.5(PVIN_B1_2) U22.6(PVIN_LDO1) U22.13(VSYS) U22.22(PVIN_LDO34) U22.26(PVIN_B3) U22.30(PVIN_B2) U29.1(VIN1) U29.2(VIN2) U29.4(VBIAS) U59.5(VCC) U67.1(BIAS) U125.B2(VIN)
VCC_3V3_MAIN_PG: R385.1 R440.2 TP101.1(TP) U59.6(C) U67.5(PGOOD)
VCC_3V3_SYS: C1.1 C2.1 C6.2 C7.2 C15.2 C38.1 C40.1 C44.1 C59.1 C60.1 C64.1 C66.1 C67.1 C81.2 C108.2 C113.2 C116.2 C119.1 C135.1 C141.1 C159.1 C176.2 C177.1 C178.2 C180.2 C181.2 C182.2 C183.2 C186.1 C188.2 C189.1 C193.2 C194.1 C202.1 C204.2 C208.2 C230.1 C232.2 C312.1 C313.1 C318.1 C322.1 C323.1 C333.1 C334.2 C335.1 C351.1 C352.1 C362.1 C370.1 C372.1 C373.1 C377.2 C378.1 C379.2 C386.1 C413.2 C419.1 C426.2 C427.1 C432.2 C433.2 C435.2 C436.2 C437.2 C441.2 C442.2 C443.2 C447.2 C448.2 C457.2 C458.2 C460.2 C466.2 C471.2 C473.2 C476.2 C477.2 C479.2 C563.1 C567.1 C570.1 C577.1 C579.1 C581.1 C583.1 C585.1 C588.1 FB1.2 FL16.1 FL18.2 FL22.1 J1.30 J1.32 J1.34 J1.36 J2.2(3-3V#2) J2.4(3-3V#4) J2.72(3-3V#72) J2.74(3-3V#74) J10.1 J19.5 R3.2 R6.1 R8.1 R9.2 R22.1 R23.1 R24.1 R25.1 R29.1 R30.1 R31.1 R33.1 R39.2 R56.2 R61.2 R64.2 R67.2 R68.2 R69.2 R86.2 R101.2 R122.2 R127.2 R128.2 R130.2 R139.2 R141.2 R151.1 R154.1 R155.2 R167.2 R172.2 R173.2 R177.2 R178.2 R179.2 R182.1 R238.1 R239.1 R257.2 R258.2 R259.2 R263.2 R278.2 R279.2 R289.2 R301.2 R342.2 R365.1 R367.1 R369.2 R370.2 R373.2 R374.2 R376.2 R380.2 R381.1 R395.2 R402.2 R407.2 R412.1 R416.1 R418.2 R419.1 R424.1 R431.1 R457.2 R462.2 R463.2 R468.2 R472.2 R473.1 R474.1 R492.2 R495.2 R496.1 R510.2 R521.2 R527.2 R530.2 R531.1 R532.1 R534.2 R535.2 R538.1 R547.1 R554.1 R557.2 R560.1 R561.2 R562.1 R566.1 R581.1 R589.2 R591.2 R630.1 R634.2 R640.2 R642.2 R645.2 R647.1 R648.2 R650.2 R652.2 R653.2 R654.1 R655.2 R656.2 R657.2 R658.2 TP54.1(TP) U2.8(VCCB) U3.27(VCCP) U3.31(VCC) U4.14(VCC) U9.4(VCC) U13.1(VIN) U16.B1(VS) U17.B1(VS) U18.4(IN) U19.8(VCCB) U21.E6(VCC#E6) U21.F5(VCC#F5) U21.J10(VCC#J10) U21.K9(VCC#K9) U24.4(V+) U26.16(VCC) U28.8(VCC) U29.7(VOUT1) U29.8(VOUT2) U31.5(VCC) U32.8(VCCB) U39.16(VCC) U40.11(VCCB) U41.5(VCC) U42.16(VCC) U43.16(VCC) U44.3(VCCA) U46.A2(VIN) U47.5(VCC) U48.4(V+) U50.24(VCCA) U52.5(VCC) U55.19(VDDIO#19) U55.30(VDDIO#30) U55.41(VDDIO#41) U57.6(VIN) U58.B1(VS) U58.B3(A0) U58.C3(A1) U60.B1(VS) U60.C3(A1) U61.B1(VS) U62.5(VCC) U63.B1(VS) U63.B3(A0) U65.A2(VIN) U70.27(VCCP) U70.31(VCC) U73.23(VCCB1) U73.24(VCCB2) U75.23(VCCB1) U75.24(VCCB2) U76.5(VCC) U79.1(VCCA) U79.8(VCCB) U80.5(VCC) U81.8(VCC) U82.1(VCCA) U83.3(VCCA) U84.3(VCCA) U85.1(VCCA) U87.2(VCCB) U87.3(VCCA) U89.5(VCC) U90.5(VCC) U91.3(VCCA) U92.3(VCCA) U95.1(VCCA) U95.8(VCCB) U96.3(VCCA) U97.7(VCCB) U98.19(VCCB) U127.19(VDDIO#19) U127.30(VDDIO#30) U127.41(VDDIO#41) U128.5(VCC)
VCC_5V0: C13.1 C14.1 C109.1 C111.1 C144.1 C145.1 C146.1 C187.1 C217.1 C414.1 C420.1 C421.1 C534.1 C535.1 Q10.4(D1) Q10.7(D2) R202.2 R208.1 R209.1 R288.2 R291.1 R465.1 TP76.1(TP) U7.2(IN) U7.3(EN2) U23.3(IN) U33.7(VOUT) U45.A2(VIN) U50.11(VCC5V)
VCC_5V0_FB: R206.1 R209.2 U33.5(FB)
VCC_5V0_HDMICONN: C212.1 J5.18 U50.13(5V_OUT)
VCC_5V0_PG: R202.1 U33.2(PG) U89.3(B)
VCC_CORE: C70.1 C77.2 C79.2 L1.2 R106.2 TP39.1(TP) U22.1(FB_B1)
VCC_CSI_IO: C4.1 C12.1 C478.2 C480.2 J1.38 J1.40 R16.2 R19.2 R20.1 R567.1 R568.1 R573.2 R575.2 U97.3(VCCA) U98.2(VCCA)
VDD1_LPDDR4_1V8: C78.1 C80.2 C88.1 C90.2 C91.2 C94.2 C95.2 C332.2 C337.2 C353.2 C355.2 FL10.2 U20.F1(VDD1#F1) U20.F12(VDD1#F12) U20.G4(VDD1#G4) U20.G9(VDD1#G9) U20.T4(VDD1#T4) U20.T9(VDD1#T9) U20.U1(VDD1#U1) U20.U12(VDD1#U12)
VDD_1V0: C45.1 C46.1 C47.1 C52.1 C55.1 C56.1 C57.1 C317.1 C324.1 C325.1 C326.1 C564.1 C565.1 C568.1 C569.1 C572.1 C574.1 C576.1 C578.1 C580.1 C586.1 TP35.1(TP) U55.6(VDD1P0#6) U55.24(VDD1P0#24) U55.31(VDD1P0#31) U55.42(VDD1P0#42) U56.1(OUT) U127.6(VDD1P0#6) U127.24(VDD1P0#24) U127.31(VDD1P0#31) U127.42(VDD1P0#42)
VDD_1V2: C102.1 C201.1 C227.1 FB2.2 FB3.2 TP53.1(TP) U22.23(VLDO4)
VDD_2V5: C50.1 C51.1 C61.1 C63.1 C315.1 C319.1 C321.1 C340.1 C342.1 C566.1 C573.1 C575.1 C582.1 C584.1 C587.1 L8.2 R386.2 R389.1 TP40.1(TP) U55.3(VDDA2P5#3) U55.9(VDDA2P5#9) U56.4(IN) U127.3(VDDA2P5#3) U127.9(VDDA2P5#9)
VDD_2V5_FB: C340.2 R389.2 R390.1 U57.3(FB)
VDD_CANUART: C42.1 C302.1 C311.1 R587.2 U12.H8(VDD_CANUART)
VDD_CANUART_EN: R586.2 R588.2 U125.A2(EN)
VDD_CORE: C26.1 C27.1 C32.1 C241.1 C242.1 C249.1 C253.1 C254.1 C256.1 C258.1 C262.1 C263.1 C264.1 C268.1 C269.1 C271.1 C273.1 C274.1 C282.1 C285.1 C286.1 C292.1 C297.1 C303.1 FL15.2 R106.3 U12.H12(VDD_CORE#H12) U12.H14(VDD_CORE#H14) U12.J9(VDD_CORE#J9) U12.J11(VDD_CORE#J11) U12.J13(VDD_CORE#J13) U12.K10(VDD_CORE#K10) U12.K14(VDD_CORE#K14) U12.L11(VDD_CORE#L11) U12.L13(VDD_CORE#L13) U12.M8(VDD_CORE#M8) U12.M12(VDD_CORE#M12) U12.M14(VDD_CORE#M14) U12.N9(VDD_CORE#N9) U12.N11(VDD_CORE#N11) U12.N13(VDD_CORE#N13) U12.P8(VDD_CORE#P8) U12.P11(VDDA_CORE_USB) U12.P12(VDDA_CORE_CSIRX0)
VDD_LPDDR4: C72.2 C74.1 C83.2 C92.2 C93.2 C97.2 C98.1 C99.2 C104.2 C105.2 C106.1 C298.1 C301.1 C308.1 C309.1 C314.1 C316.1 C330.2 C331.2 C336.2 C339.2 C346.2 C347.2 C348.1 C349.1 C356.2 C357.2 C360.1 C366.1 C367.2 R93.2 R100.1 R129.3 R384.2 U12.C1(VDDS_DDR#C1) U12.J8(VDDS_DDR#J8) U12.K7(VDDS_DDR#K7) U12.K9(VDDS_DDR#K9) U12.L7(VDDS_DDR_C) U12.L8(VDDS_DDR#L8) U12.U1(VDDS_DDR#U1) U20.A4(VDD2#A4) U20.A9(VDD2#A9) U20.AA3(VDDQ#AA3) U20.AA5(VDDQ#AA5) U20.AA8(VDDQ#AA8) U20.AA10(VDDQ#AA10) U20.AB4(VDD2#AB4) U20.AB9(VDD2#AB9) U20.B3(VDDQ#B3) U20.B5(VDDQ#B5) U20.B8(VDDQ#B8) U20.B10(VDDQ#B10) U20.D1(VDDQ#D1) U20.D5(VDDQ#D5) U20.D8(VDDQ#D8) U20.D12(VDDQ#D12) U20.F3(VDDQ#F3) U20.F5(VDD2#F5) U20.F8(VDD2#F8) U20.F10(VDDQ#F10) U20.H1(VDD2#H1) U20.H5(VDD2#H5) U20.H8(VDD2#H8) U20.H12(VDD2#H12) U20.K1(VDD2#K1) U20.K3(VDD2#K3) U20.K10(VDD2#K10) U20.K12(VDD2#K12) U20.N1(VDD2#N1) U20.N3(VDD2#N3) U20.N10(VDD2#N10) U20.N12(VDD2#N12) U20.R1(VDD2#R1) U20.R5(VDD2#R5) U20.R8(VDD2#R8) U20.R12(VDD2#R12) U20.U3(VDDQ#U3) U20.U5(VDD2#U5) U20.U8(VDD2#U8) U20.U10(VDDQ#U10) U20.W1(VDDQ#W1) U20.W5(VDDQ#W5) U20.W8(VDDQ#W8) U20.W12(VDDQ#W12)
VDD_MMC1: C39.1 FL8.1 U13.5(QOD) U13.6(VOUT)
VDD_MMC1_SD: C48.2 C49.2 FL8.2 J21.4(VDD) U14.1(VCC)
VDDA1V8: C101.1 C368.2 R134.2 TP52.1(TP) U22.21(VLDO3)
VDDA_1V8: C277.1 FL3.1 FL4.1 FL12.1 R134.3 U12.R11(VDDA_1P8_USB)
VDDA_1V8_FB1: C225.1 C226.1 C235.1 C255.1 C265.1 C281.1 C287.1 C307.1 FL12.2 U12.F16(VDDA_TEMP1) U12.H10(VDDA_MCU) U12.K12(VDDA_PLL2) U12.M7(VDDA_TEMP0) U12.N10(VDDA_PLL0) U12.P14(VDDA_PLL1)
VDDA_1V8_FB2: C28.1 C31.1 C275.1 C296.1 C299.1 FL3.2 U12.P9(VDDA_1P8_OLDI0#P9) U12.R9(VDDA_1P8_OLDI0#R9) U12.R12(VDDA_1P8_CSIRX0)
VDDA_1V8_FB_OSC: C25.1 C306.1 FL4.2 U12.J7(VDDS_OSC0)
VDDA_DDR_PLL0: C295.1 C329.1 FL15.1 U12.L9(VDDA_DDR_PLL0)
VDDA_SYS_MON: C533.1 R115.1 R387.2 U12.F6(VMON_ER_VSYS)
VDDC_1V2: C161.1 C162.1 C434.2 U36.87(VDDC#87) U36.115(VDDC#115)
VDDIM: C343.1 C344.1 U21.C2(VDDIM)
VDDR_CORE: C33.1 C34.2 C35.1 C36.1 C37.1 C270.1 C288.1 C294.1 R136.3 R406.1 U12.H11(VDDR_CORE#H11) U12.M10(VDDR_CORE#M10) U12.M13(VDDR_CORE#M13)
VDDSHV_CANUART: C115.1 C310.1 C327.1 C328.1 FL14.2 R80.1 R117.2 R149.1 R516.1 R528.1 U12.G7(VDDSHV_CANUART#G7) U12.H7(VDDSHV_CANUART#H7) U27.8(VCC)
VDDSHV_SDIO: C54.2 C87.1 FL9.1 R73.2 R74.2 R75.2 R88.2 R89.2 R90.2 TP41.1(TP) U15.10(VCC) U22.7(VLDO1)
ADCIN1: R452.2 R454.1 U68.6(ADCIN1)
ADCIN2: R448.1 R449.2 U68.10(ADCIN2)
ADDR_IO_EXP: R470.2 U70.26(ADDR)
ADDR_IO_EXP1: R9.1 U3.26(ADDR)
AUD_RSTN: R469.2 U66.33(R\E\S\E\T\) U71.4(Y)
AUDIO_EXT_REFCLK1: R348.2 U12.C16(MCASP0_AFSX)
AUDIO_MSTRCLK: R430.1 U66.37(MCLK)
BOOTMODE0: RA8.2 U75.14(B8)
BOOTMODE1: RA8.4 U75.15(B7)
BOOTMODE2: RA8.1 U75.16(B6)
BOOTMODE3: RA8.3 U75.17(B5)
BOOTMODE4: RA7.3 U75.18(B4)
BOOTMODE5: RA7.2 U75.19(B3)
BOOTMODE6: RA7.4 U75.20(B2)
BOOTMODE7: RA7.1 U75.21(B1)
BOOTMODE8: RA6.1 U73.14(B8)
BOOTMODE9: RA6.2 U73.15(B7)
BOOTMODE10: RA5.1 U73.16(B6)
BOOTMODE11: RA5.4 U73.17(B5)
BOOTMODE12: RA5.2 U73.18(B4)
BOOTMODE13: RA5.3 U73.19(B3)
BOOTMODE14: RA6.3 U73.20(B2)
BOOTMODE15: RA6.4 U73.21(B1)
BOOTMODE_I2C_SCL: R544.1 R553.1 R555.2 TP87.1(TP) U74.29(SCL)
BOOTMODE_I2C_SDA: R536.1 R537.2 R546.1 TP88.1(TP) U74.30(SDA)
BOOTMODEON: R237.2 U34.4(Y) U73.22(O\E\) U75.22(O\E\)
BT_EN_SOC: J2.54(W_DISABLE2#) R258.1 U12.E7(MCU_SPI0_CS0)
BT_UART_WAKE_SOC: J2.20(UART_WAKE#) R279.1 U70.12(P13)
CAN_FD_WKUP_HDR_INH: J10.5 R82.1
CAN_FD_WKUP_SW_INH: R78.2 U27.7(1Y)
CAP_VDDS0: C284.1 U12.G12(CAP_VDDS0)
CAP_VDDS1: C234.1 U12.L15(CAP_VDDS1)
CAP_VDDS2: C266.1 U12.R13(CAP_VDDS2)
CAP_VDDS3: C240.1 U12.M15(CAP_VDDS3)
CAP_VDDS4: C304.1 U12.N8(CAP_VDDS4)
CAP_VDDS5: C246.1 U12.G15(CAP_VDDS5)
CAP_VDDS6: C239.1 U12.J15(CAP_VDDS6)
CAP_VDDS_CANUART: C300.1 U12.G8(CAP_VDDS_CANUART)
CAP_VDDS_MCU: C278.1 U12.G11(CAP_VDDS_MCU)
CBOOT: C405.1 U67.13(RBOOT) U67.14(CBOOT)
CH1_LVDS_A0N: J22.11 U12.AA2(OLDI0_A0N)
CH1_LVDS_A0P: J22.12 U12.AA3(OLDI0_A0P)
CH1_LVDS_A1N: J22.14 U12.V5(OLDI0_A1N)
CH1_LVDS_A1P: J22.15 U12.V6(OLDI0_A1P)
CH1_LVDS_A2N: J22.20 U12.U7(OLDI0_A2N)
CH1_LVDS_A2P: J22.21 U12.U6(OLDI0_A2P)
CH1_LVDS_A3N: J22.23 U12.W6(OLDI0_A3N)
CH1_LVDS_A3P: J22.24 U12.W5(OLDI0_A3P)
CH1_LVDS_CLKN: J22.17 U12.V7(OLDI0_CLK0N)
CH1_LVDS_CLKP: J22.18 U12.V8(OLDI0_CLK0P)
CH2_LVDS_A0N: J22.26 U12.AA4(OLDI0_A4N)
CH2_LVDS_A0P: J22.27 U12.Y5(OLDI0_A4P)
CH2_LVDS_A1N: J22.29 U12.AA6(OLDI0_A5N)
CH2_LVDS_A1P: J22.30 U12.AA5(OLDI0_A5P)
CH2_LVDS_A2N: J22.35 U12.AA10(OLDI0_A6N)
CH2_LVDS_A2P: J22.36 U12.Y9(OLDI0_A6P)
CH2_LVDS_A3N: J22.38 U12.AA8(OLDI0_A7N)
CH2_LVDS_A3P: J22.39 U12.Y8(OLDI0_A7P)
CH2_LVDS_CLKN: J22.32 U12.Y7(OLDI0_CLK1N)
CH2_LVDS_CLKP: J22.33 U12.AA7(OLDI0_CLK1P)
CLKOUT0: R12.2 R14.2 U6.1(CLKIN)
CLKOUT_OSC: R14.1 U5.3(OUTPUT)
COM_SDIO_CMD: J2.11(SDIO_CMD) R275.1 R285.1
COM_SDIO_D0: J2.13(SDIO_DATA0) R277.1 R287.1
COM_SDIO_D1: J2.15(SDIO_DATA1) R276.1 R286.1
COM_SDIO_D2: J2.17(SDIO_DATA2) R274.1 R284.1
COM_SDIO_D3: J2.19(SDIO_DATA3) R273.1 R283.1
CONN_MCU_PORZ: J10.28 R472.1 U72.1(A)
CONN_MCU_RESETZ: J10.25 Q4.1(G) R418.1
CPSW1_GPIO_0: J7.14 Q7.1(D1) Q7.2(D2) Q7.5(D3) Q7.6(D4) Q7.8(D5) R395.1
CPSW1_LED_1000: J7.12 Q5.1(D1) Q5.2(D2) Q5.5(D3) Q5.6(D4) Q5.8(D5)
CPSW1_LED_ACT: J7.13 Q6.1(D1) Q6.2(D2) Q6.5(D3) Q6.6(D4) Q6.8(D5) R373.1
CPSW2_GPIO_0: J27.14 Q20.1(D1) Q20.2(D2) Q20.5(D3) Q20.6(D4) Q20.8(D5) R656.1
CPSW2_LED_1000: J27.12 Q19.1(D1) Q19.2(D2) Q19.5(D3) Q19.6(D4) Q19.8(D5)
CPSW2_LED_ACT: J27.13 Q21.1(D1) Q21.2(D2) Q21.5(D3) Q21.6(D4) Q21.8(D5) R655.1
CPSW_ETH1_D0N: J7.10(MX0-) U55.2(TD_M_A)
CPSW_ETH1_D0P: J7.9(MX0+) U55.1(TD_P_A)
CPSW_ETH1_D1M: J7.8(MX1-) U55.5(TD_M_B)
CPSW_ETH1_D1P: J7.7(MX1+) U55.4(TD_P_B)
CPSW_ETH1_D2M: J7.6(MX2-) U55.8(TD_M_C)
CPSW_ETH1_D2P: J7.5(MX2+) U55.7(TD_P_C)
CPSW_ETH1_D3M: J7.4(MX3-) U55.11(TD_M_D)
CPSW_ETH1_D3P: J7.3(MX3+) U55.10(TD_P_D)
CPSW_ETH1_GPIO_0: R64.1 R363.2 R372.1 R394.1 TP23.1(TP)
CPSW_ETH1_GPIO_1: R69.1 R362.2 R371.1 TP26.1(TP)
CPSW_ETH1_LED0: TP27.1(TP) U55.47(LED_0)
CPSW_ETH1_LED_1000: R77.2 R352.1 R369.1 TP28.1(TP) U55.46(LED_1)
CPSW_ETH1_LED_ACT: R68.1 R364.2 R393.1 TP24.1(TP) U55.45(LED_2)
CPSW_ETH2_D0N: J27.10(MX0-) U127.2(TD_M_A)
CPSW_ETH2_D0P: J27.9(MX0+) U127.1(TD_P_A)
CPSW_ETH2_D1M: J27.8(MX1-) U127.5(TD_M_B)
CPSW_ETH2_D1P: J27.7(MX1+) U127.4(TD_P_B)
CPSW_ETH2_D2M: J27.6(MX2-) U127.8(TD_M_C)
CPSW_ETH2_D2P: J27.5(MX2+) U127.7(TD_P_C)
CPSW_ETH2_D3M: J27.4(MX3-) U127.11(TD_M_D)
CPSW_ETH2_D3P: J27.3(MX3+) U127.10(TD_P_D)
CPSW_ETH2_GPIO_0: R627.1 R641.1 R643.2 R645.1 TP121.1(TP)
CPSW_ETH2_GPIO_1: R628.1 R642.1 R649.2 TP122.1(TP)
CPSW_ETH2_LED0: TP123.1(TP) U127.47(LED_0)
CPSW_ETH2_LED_1000: R629.1 R633.2 R648.1 TP119.1(TP) U127.46(LED_1)
CPSW_ETH2_LED_ACT: R638.2 R650.1 R651.1 TP120.1(TP) U127.45(LED_2)
CPSW_RGMII1_ETH1_CLK: R15.2 U55.15(XI)
CPSW_RGMII1_ETH1_CLK_OUT: TP38.1(TP) U55.18(CLK_OUT)
CPSW_RGMII1_ETH1_RBIAS: C320.2 R378.1 U55.12(RBIAS)
CPSW_RGMII1_ETH2_RBIAS: C562.2 R636.1 U127.12(RBIAS)
CPSW_RGMII1_MDC: R102.2 R380.1 U55.16(MDC)
CPSW_RGMII1_MDIO: R98.2 R381.2 U55.17(MDIO)
CPSW_RGMII1_RD0: R83.2 R376.1 U12.W15(RGMII1_RD0) U55.33(RX_D0)
CPSW_RGMII1_RD1: U12.Y16(RGMII1_RD1) U55.34(RX_D1)
CPSW_RGMII1_RD2: R81.2 R374.1 U12.AA17(RGMII1_RD2) U55.35(RX_D2)
CPSW_RGMII1_RD3: U12.Y15(RGMII1_RD3) U55.36(RX_D3)
CPSW_RGMII1_RESETN: R460.1 U31.4(Y) U55.43(RESET_N)
CPSW_RGMII1_RX_CTL: R367.2 R368.2 U12.W14(RGMII1_RX_CTL) U55.38(RX_DV/RX_CTRL)
CPSW_RGMII1_RXC: R377.1 U12.AA16(RGMII1_RXC)
CPSW_RGMII1_TD0: U12.U14(RGMII1_TD0) U55.28(TX_D0)
CPSW_RGMII1_TD1: U12.AA19(RGMII1_TD1) U55.27(TX_D1)
CPSW_RGMII1_TD2: U12.Y17(RGMII1_TD2) U55.26(TX_D2)
CPSW_RGMII1_TD3: U12.AA18(RGMII1_TD3) U55.25(TX_D3)
CPSW_RGMII1_TX_CTL: U12.V15(RGMII1_TX_CTL) U55.37(TX_EN/TX_CTRL)
CPSW_RGMII1_TXC: R346.2 U55.29(GTX_CLK)
CPSW_RGMII2_ETH2_CLK: R26.2 U127.15(XI)
CPSW_RGMII2_ETH2_CLK_OUT: TP124.1(TP) U127.18(CLK_OUT)
CPSW_RGMII2_MDC: R644.2 R652.1 U127.16(MDC)
CPSW_RGMII2_MDIO: R630.2 R646.2 U127.17(MDIO)
CPSW_RGMII2_RD0: R631.2 R653.1 U12.W18(RGMII2_RD0) U127.33(RX_D0)
CPSW_RGMII2_RD1: U12.Y20(RGMII2_RD1) U127.34(RX_D1)
CPSW_RGMII2_RD2: R637.2 R640.1 U12.Y19(RGMII2_RD2) U127.35(RX_D2)
CPSW_RGMII2_RD3: U12.W20(RGMII2_RD3) U127.36(RX_D3)
CPSW_RGMII2_RESETN: R661.1 U127.43(RESET_N) U128.4(Y)
CPSW_RGMII2_RX_CTL: R635.2 R654.2 U12.W19(RGMII2_RX_CTL) U127.38(RX_DV/RX_CTRL)
CPSW_RGMII2_RXC: R632.1 U12.V18(RGMII2_RXC)
CPSW_RGMII2_TD0: U12.AA20(RGMII2_TD0) U127.28(TX_D0)
CPSW_RGMII2_TD1: U12.U15(RGMII2_TD1) U127.27(TX_D1)
CPSW_RGMII2_TD2: U12.W17(RGMII2_TD2) U127.26(TX_D2)
CPSW_RGMII2_TD3: U12.V16(RGMII2_TD3) U127.25(TX_D3)
CPSW_RGMII2_TX_CTL: U12.Y21(RGMII2_TX_CTL) U127.37(TX_EN/TX_CTRL)
CPSW_RGMII2_TXC: R43.2 U127.29(GTX_CLK)
CPSW_RGMII2_TXC_R: R43.1 U12.Y18(RGMII2_TXC)
CPSW_RGMII_INTN: R63.2 R370.1 R634.1 U55.44(INT/PWDN) U127.44(INT/PWDN)
CPSW_RGMII_INTN/PRU_INTN: R55.1 R63.1 R433.1
CPSW_RGMII_TXC_R: R346.1 U12.W16(RGMII1_TXC)
CSI0_RXCLKN: J1.7 U12.AA14(CSI0_RXCLKN)
CSI0_RXCLKP: J1.5 U12.AA13(CSI0_RXCLKP)
CSI0_RXN0: J1.11 U12.Y13(CSI0_RXN0)
CSI0_RXN1: J1.15 U12.V13(CSI0_RXN1)
CSI0_RXN2: J1.19 U12.U12(CSI0_RXN2)
CSI0_RXN3: J1.23 U12.W12(CSI0_RXN3)
CSI0_RXP0: J1.9 U12.Y12(CSI0_RXP0)
CSI0_RXP1: J1.13 U12.V12(CSI0_RXP1)
CSI0_RXP2: J1.17 U12.U11(CSI0_RXP2)
CSI0_RXP3: J1.21 U12.W11(CSI0_RXP3)
CSI0_RXRCALIB: R356.2 U12.T11(CSI0_RXRCALIB)
CSI_GPIO0: U70.14(P15) U98.20(B1)
CSI_GPIO0_BUFF: J1.6 U98.1(A1)
CSI_GPIO1: U70.15(P16) U98.18(B2)
CSI_GPIO1_BUFF: J1.8 U98.3(A2)
CSI_GPIO2: U43.6(2B2) U98.17(B3)
CSI_GPIO2_BUFF: J1.18 U98.4(A3)
CSI_GPIO3: U43.3(1B2) U98.16(B4)
CSI_GPIO3_BUFF: J1.20 U98.5(A4)
CSI_GPIO4: U43.10(3B2) U98.15(B5)
CSI_GPIO4_BUFF: J1.22 U98.6(A5)
CSI_I2C2_NINT1: R22.2 U4.8(I\N\T\1\)
CSI_I2C2_SCL: R24.2 U4.10(SC1) U97.8(SCL_B)
CSI_I2C2_SCL_BUFF: J1.2 R567.2 U97.5(SCL_A)
CSI_I2C2_SDA: R23.2 U4.9(SD1) U97.1(SDA_B)
CSI_I2C2_SDA_BUFF: J1.4 R568.2 U97.4(SDA_A)
CSI_I2C_LT_EN: R575.1 R576.2 U97.6(OE)
CSI_LT_EN: R573.1 R574.2 U98.10(OE)
CSI_REFCLK: J1.10 R18.2 TP2.1(TP)
CSI_RSTZ: R4.1 U3.10(P11) U98.14(B6)
CSI_RSTZ_BUFF: J1.14 U98.7(A6)
CSI_VLDO_SEL: R13.1 U3.23(P26) U7.1(EN1)
DEBOUNCE_CAN_FD_WKUP: C114.2 D4.2 R149.2 SW2.2 SW2.3 U27.1(1A)
DEBOUNCE_GPIO_INT_MCU: C454.2 D12.2 Q12.2(S) R531.2 SW6.2 SW6.3 U81.3(2A)
DEBOUNCE_MCU_RESETZ: C140.2 Q4.2(S) R182.2 TP70.1(TP) U81.1(1A)
DEBOUNCE_SOC_WARMRESETN: C455.2 D13.2 Q13.2(S) R532.2 SW5.2 SW5.3 U81.6(3A)
DIR: R483.1 U73.2(DIR) U75.2(DIR)
DRAIN1: U68.8(DRAIN1_1) U68.15(DRAIN1_2) U68.19(DRAIN1_3) U68.58(DRAIN1_4)
DRAIN2: U68.7(DRAIN2_1) U68.52(DRAIN2_2) U68.56(DRAIN2_3) U68.57(DRAIN2_4)
EEPROM_A0: R154.2 U28.1(E0)
EEPROM_A1: R153.1 U28.2(E1)
EEPROM_A2: R152.1 U28.3(E2)
EEPROM_VDD: FL18.1 J22.1
EEPROM_WP: R423.1 U28.7(W\C\)
EMMC_RSTN: R138.2 U21.K5(RST_N) U25.4(Y)
ETH1_EARTH: C338.1 J7.15(SH1) J7.16(SH2) R354.1
ETH2_EARTH: C571.1 J27.15(SH1) J27.16(SH2) R639.1
ETH_CAN_INH: R76.2 R78.1 R79.2 R82.2
ETH_CAN_INH_PMIC: R76.1 R405.2 R590.2 U22.25(EN/PB/VSENSE)
ETH_CAN_INH_SOC: R79.1 R80.2 R585.1
EXP_CLKOUT0: J3.7 R52.1
EXP_EHRPWM1_B: J3.33 U12.D18(MCASP0_AXR0)
EXP_GPIO0_14: J3.22 U19.7(B1)
EXP_GPIO0_14_LT: U12.E18(OSPI0_CSN3) U19.2(A1)
EXP_GPIO0_32: J3.30 RA4.5
EXP_GPIO0_33: J3.31 U12.K21(GPMC0_OEN_REN)
EXP_GPIO0_36: J3.29 U12.K18(GPMC0_BE1N)
EXP_GPIO0_38: J3.16 U12.P17(GPMC0_WAIT1)
EXP_GPIO0_39: J3.18 U12.J20(GPMC0_WPN)
EXP_GPIO0_40/PR0_ECAP0_IN_APWM_: J3.32 U12.J19(GPMC0_DIR)
EXP_GPIO0_41: J3.37 U12.J18(GPMC0_CSN0)
EXP_GPIO0_42: J3.13 U12.H17(GPMC0_CSN1)
EXP_GPIO1_22: J3.15 U12.B14(UART0_CTSN)
EXP_HAT_DETECT: J3.39 R173.1 U70.8(P07)
EXP_I2C2_NINT0: R6.2 U4.4(I\N\T\0\)
EXP_I2C2_SCL: J3.5 R33.2 U4.6(SC0)
EXP_I2C2_SDA: J3.3 R31.2 U4.5(SD0)
EXP_PS_3V3_EN: R293.2 U46.B2(ON) U70.6(P05)
EXP_PS_5V0_EN: R290.2 U45.C2(ON) U70.7(P06)
EXP_SPI0_CLK: J3.23 U43.2(1B1)
EXP_SPI0_CS0: J3.24 R299.2 U43.11(3B1)
EXP_SPI0_CS1: J3.26 R298.2 U12.D13(SPI0_CS1)
EXP_SPI0_D0: J3.19 U43.5(2B1)
EXP_SPI0_D1: J3.21 U12.A14(SPI0_D1)
EXP_SPI2_CLK: J3.40 U42.5(2B1)
EXP_SPI2_CS0/EHRPWM0_A: J3.12 R294.2 U42.2(1B1)
EXP_SPI2_CS1: J3.11 R295.2 U12.C17(MCASP0_ACLKX)
EXP_SPI2_CS2: J3.36 R297.2 U12.A18(MCASP0_AXR1)
EXP_SPI2_D0: J3.38 U42.11(3B1)
EXP_SPI2_D1/ECAP2_IN_APWM_OUT: J3.35 U42.14(4B1)
EXP_UART5_RXD: J3.10 U12.B13(MCAN0_TX)
EXP_UART5_TXD: J3.8 U12.A15(MCAN0_RX)
EXT_CLKOUT0: R12.1 R53.1
EXT_CLKOUT0_R: R52.2 R53.2 U12.C14(EXT_REFCLK1)
EXTINTN: R55.2 R126.1 U12.B16(EXTINTN)
FT4232_DO: R499.1 R506.2 U86.4(DO)
FT4232_EECLK: R500.1 U37.62(EECLK) U86.2(CLK)
FT4232_EECS: R501.1 U37.63(EECS) U86.1(CS)
FT4232_EEDATA: R506.1 U37.61(EEDATA) U86.3(DI)
FT4232_MCU_UART0_CTS_3V3: U37.53(DDBUS2) U83.12(2B2)
FT4232_MCU_UART0_RTS_3V3: U37.54(DDBUS3) U83.14(1B2)
FT4232_MCU_UART0_RX_3V3: U37.48(DDBUS0) U83.13(2B1)
FT4232_MCU_UART0_TX_3V3: U37.52(DDBUS1) U83.15(1B1)
FT4232_REF: R548.2 U37.6(REF)
FT4232_RESET: C167.2 R251.1 U37.14(R\E\S\E\T\)
FT4232_SOC_UART0_RX_3V3: U37.16(ADBUS0) U92.13(2B1)
FT4232_SOC_UART0_TX_3V3: U37.17(ADBUS1) U92.15(1B1)
FT4232_SOC_UART1_CTS_3V3: U37.28(BDBUS2) U96.12(2B2)
FT4232_SOC_UART1_RTS_3V3: U37.29(BDBUS3) U96.14(1B2)
FT4232_SOC_UART1_RX_3V3: U37.26(BDBUS0) U96.13(2B1)
FT4232_SOC_UART1_TX_3V3: U37.27(BDBUS1) U96.15(1B1)
FT4232_USB_DM: J17.2(D-) U35.5(IO2) U37.7(DM)
FT4232_USB_DP: J17.3(D+) U35.3(IO1) U37.8(DP)
FT4232_USB_VBUS: C465.2 C468.2 D8.2 J17.1(VBUS) U35.1(VCC) U94.4(EN) U94.6(IN)
FT4232_WKUP_UART0_CTS_3V3: U37.40(CDBUS2) U91.12(2B2)
FT4232_WKUP_UART0_RTS_3V3: U37.41(CDBUS3) U91.14(1B2)
FT4232_WKUP_UART0_RX_3V3: U37.38(CDBUS0) U91.13(2B1)
FT4232_WKUP_UART0_TX_3V3: U37.39(CDBUS1) U91.15(1B1)
FT_PWREN#: R243.1 U37.60(P\W\R\E\N\)
GPIO1_23_INTN: R467.1 R505.2 U12.C13(UART0_RTSN)
GPIO_AUD_RSTN: R451.1 R456.2 U70.9(P10) U71.1(A)
GPIO_CPSW1_RST: R176.1 R177.1 U31.1(A) U70.2(P01)
GPIO_CPSW2_RST: R658.1 R659.1 U70.1(P00) U128.1(A)
GPIO_EMMC_RSTN: R141.1 U25.1(A) U70.10(P11)
GPIO_HDMI_RSTN: R300.2 R301.1 U47.1(A) U70.13(P14)
GPIO_MCU: R505.1 U81.5(2Y)
GPIO_OLDI_RSTN: R407.1 U3.19(P22) U62.1(A)
GPIO_OSPI_RSTN: R332.1 U8.1(A) U12.F17(OSPI0_CSN1)
HDMI_AUDD1: TP16.1(TP) U11.40(SD1)
HDMI_AUDD2: TP15.1(TP) U11.39(SD2)
HDMI_AUDD3: TP14.1(TP) U11.37(SD3)
HDMI_CEC: U11.71(CEC_A) U50.1(CEC_A)
HDMI_CEC_D: TP17.1(TP) U11.50(CEC_D)
HDMI_CLK+: J5.10 U11.59(TXC+) U50.16(CLK+)
HDMI_CLK-: J5.12 U11.58(TXC-) U50.15(CLK-)
HDMI_CONN_I2CSCL: J5.15 U50.8(SCL_B)
HDMI_CONN_I2CSDA: J5.16 U50.9(SDA_B)
HDMI_CONNCEC: J5.13 U50.7(CEC_B)
HDMI_EARTH: FL6.2 J5.20 J5.21 J5.22 J5.23
HDMI_EXTSWING: R339.1 U11.56(EXT_SWING)
HDMI_HPD: R338.1 U11.54(HPD) U50.4(HPD_A)
HDMI_I2C_SCL: R317.2 U11.49(DSCL) U50.2(SCL_A)
HDMI_I2C_SDA: R310.2 U11.48(DSDA) U50.3(SDA_A)
HDMI_INTN: R41.2 U11.52(INT) U70.17(P20)
HDMI_MSTRCLK: R34.2 R348.1 U11.38(MCLK)
HDMI_PCLK: R329.2 U11.22(IDCK)
HDMI_RSTN: R296.2 U11.51(RESET#) U47.4(Y)
HDMI_TX0+: J5.7 U11.62(TX0+) U50.18(D0+)
HDMI_TX0-: J5.9 U11.61(TX0-) U50.17(D0-)
HDMI_TX1+: J5.4 U11.65(TX1+) U50.21(D1+)
HDMI_TX1-: J5.6 U11.64(TX1-) U50.20(D1-)
HDMI_TX2+: J5.1 U11.68(TX2+) U50.23(D2+)
HDMI_TX2-: J5.3 U11.67(TX2-) U50.22(D2-)
HDMICONN_HPD: J5.19 U50.10(HPD_B)
HFOSC0_CLKOUT_32K: R2.1 U12.B12(WKUP_CLKOUT0)
HPLOUT: C408.2 J14.2
HPLOUT_C: C408.1 U66.18(HPLOUT)
HPROUT: C409.2 J14.3
HPROUT_C: C409.1 U66.23(HPROUT)
INA_ALERT: R85.2 R86.1 R95.2 R392.2 R397.2 R409.2 R414.2 TP31.1(TP)
IO_EXP1_INTN: R3.1 U3.32(I\N\T\)
IO_EXP_ADDR: R488.1 U74.26(ADDR)
IO_EXP_INTN: R467.2 R468.1 U70.32(I\N\T\)
IO_EXP_TEST_LED: R168.1 R170.2 U70.24(P27)
JTAG_CTI_RTCK: J19.9 R558.1
JTAG_CTI_TCK: J19.11 R495.1 R512.1 U80.1(B) U90.1(B)
JTAG_DIR: R514.2 U87.4(1DIR) U87.5(2DIR)
JTAG_EMU0: J19.13 R560.2 U79.7(B1)
JTAG_EMU1: J19.14 R562.2 U79.6(B2)
JTAG_EMU_RSTN: J19.15 R547.2 U89.6(C)
JTAG_TCK: R494.1 R521.1 U87.14(1B2)
JTAG_TDI: J19.3 R535.1 U87.12(2B2)
JTAG_TDIS: J19.4 R563.2
JTAG_TDO: J19.7 U95.7(B1)
JTAG_TMS: J19.1 R530.1 U87.13(2B1)
JTAG_TRST#: J19.2 R517.2 U87.15(1B1)
LDO_1V8: C130.1 U68.35(LDO_1V8)
LDO_3V3: C122.1 C129.2 R158.1 R160.1 R161.1 R163.1 R164.1 R171.1 R436.1 R438.1 R439.1 R443.1 R449.1 R452.1 U30.8(VCC) U68.9(LDO_3V3)
LINE1L+: C392.1 TP62.1(TP)
LINE1L+_C: C392.2 U66.3(LINE1L+)
LINE1R+: C394.1 TP63.1(TP)
LINE1R+_C: C394.2 U66.5(LINE1R+)
LM61460_RT: R441.1 U67.6(RT)
